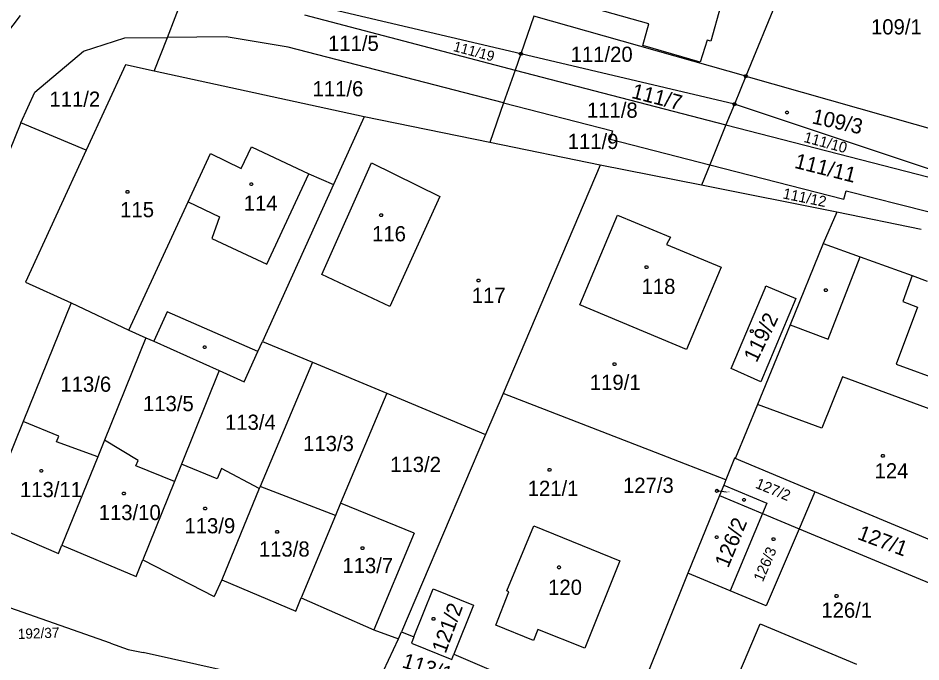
# Model space of a CAD drawing. Extents: x -634640 to -629202, y -1196156 to -1190068.
# Drawn here: x -631368.4 to -631267.3, y -1192828.3 to -1192756.2 of the extents above; entities that cross this region are included whole.
import ezdxf

# ---------------------------------------------------------------- set-up
doc = ezdxf.new("R2010")
doc.units = 0
for name, color, linetype in [('Vrstva 1', 7, 'Continuous'), ('Vrstva 2', 7, 'Continuous'), ('Vrstva 3', 7, 'Continuous'), ('Vrstva 4', 7, 'Continuous'), ('Vrstva 5', 7, 'Continuous'), ('Vrstva 7', 7, 'Continuous'), ('Vrstva 8', 7, 'Continuous')]:
    doc.layers.add(name, color=color, linetype=linetype)

msp = doc.modelspace()

# ---------------------------------------------------------------- linework, layer by layer
at = {"layer": 'Vrstva 1'}
for p, q in [((-631281.05, -1192748.42), (-631286.91, -1192762.74)), ((-631351.71, -1192758.38), (-631349.73, -1192753.3)), ((-631312.12, -1192760.23), (-631337.29, -1192754.33)), ((-631370.55, -1192759.01), (-631368.15, -1192755.91)), ((-631336.36, -1192755.87), (-631312.76, -1192762.05)), ((-631310.65, -1192756.02), (-631312.12, -1192760.23)), ((-631286.91, -1192762.74), (-631310.65, -1192756.02)), ((-631361.1, -1192759.91), (-631356.48, -1192758.44)), ((-631356.48, -1192758.44), (-631351.71, -1192758.38)), ((-631353.18, -1192762.15), (-631351.71, -1192758.38)), ((-631345.14, -1192758.3), (-631351.71, -1192758.38)), ((-631338.18, -1192759.46), (-631345.14, -1192758.3)), ((-631366.57, -1192764.5), (-631361.1, -1192759.91)), ((-631314.04, -1192765.69), (-631338.18, -1192759.46)), ((-631312.12, -1192760.23), (-631312.76, -1192762.05)), ((-631288.17, -1192765.84), (-631312.12, -1192760.23)), ((-631356.4, -1192761.45), (-631360.79, -1192771)), ((-631353.18, -1192762.15), (-631356.4, -1192761.45)), ((-631329.66, -1192767.28), (-631353.18, -1192762.15)), ((-631312.76, -1192762.05), (-631314.04, -1192765.69)), ((-631312.76, -1192762.05), (-631289.13, -1192768.17)), ((-631286.91, -1192762.74), (-631288.17, -1192765.84)), ((-631286.91, -1192762.74), (-631263.39, -1192769.4)), ((-631368.14, -1192767.96), (-631366.57, -1192764.5)), ((-631314.04, -1192765.69), (-631315.6, -1192770.16)), ((-631314.04, -1192765.69), (-631301.83, -1192768.84)), ((-631288.17, -1192765.84), (-631289.13, -1192768.17)), ((-631265.11, -1192773.56), (-631288.17, -1192765.84)), ((-631329.66, -1192767.28), (-631333.09, -1192774.84)), ((-631315.6, -1192770.16), (-631329.66, -1192767.28)), ((-631368.14, -1192767.96), (-631383.56, -1192806)), ((-631360.79, -1192771), (-631368.14, -1192767.96)), ((-631289.13, -1192768.17), (-631290.58, -1192771.73)), ((-631289.13, -1192768.17), (-631265.22, -1192774.34)), ((-631301.83, -1192768.84), (-631302.1, -1192769.76)), ((-631303.21, -1192772.69), (-631315.6, -1192770.16)), ((-631302.1, -1192769.76), (-631290.95, -1192772.64)), ((-631360.79, -1192771), (-631367.59, -1192785.78)), ((-631349.38, -1192776.81), (-631346.87, -1192771.38)), ((-631346.87, -1192771.38), (-631343.46, -1192773.07)), ((-631343.46, -1192773.07), (-631342.28, -1192770.63)), ((-631342.28, -1192770.63), (-631335.86, -1192773.65)), ((-631290.58, -1192771.73), (-631290.95, -1192772.64)), ((-631334.42, -1192784.94), (-631328.83, -1192772.44)), ((-631328.83, -1192772.44), (-631321.18, -1192776.21)), ((-631303.21, -1192772.69), (-631314.1, -1192798.26)), ((-631291.89, -1192774.93), (-631303.21, -1192772.69)), ((-631290.95, -1192772.64), (-631291.89, -1192774.93)), ((-631290.95, -1192772.64), (-631275.92, -1192776.51)), ((-631335.86, -1192773.65), (-631333.09, -1192774.84)), ((-631333.09, -1192774.84), (-631341.04, -1192792.42)), ((-631276.72, -1192777.95), (-631291.89, -1192774.93)), ((-631321.18, -1192776.21), (-631326.78, -1192788.5)), ((-631275.92, -1192776.51), (-631275.65, -1192775.56)), ((-631275.65, -1192775.56), (-631266.53, -1192777.88)), ((-631356.03, -1192791.15), (-631349.38, -1192776.81)), ((-631305.5, -1192788.35), (-631301.27, -1192778.28)), ((-631301.27, -1192778.28), (-631295.36, -1192780.76)), ((-631276.72, -1192777.95), (-631278.23, -1192781.46)), ((-631267.27, -1192779.89), (-631276.72, -1192777.95)), ((-631295.36, -1192780.76), (-631295.78, -1192781.56)), ((-631278.23, -1192781.46), (-631281.94, -1192790.56)), ((-631278.23, -1192781.46), (-631274.09, -1192782.94)), ((-631295.78, -1192781.56), (-631289.67, -1192784.13)), ((-631274.09, -1192782.94), (-631268.29, -1192785.04)), ((-631289.77, -1192784.36), (-631293.55, -1192793.33)), ((-631289.67, -1192784.13), (-631289.77, -1192784.36)), ((-631326.78, -1192788.5), (-631334.42, -1192784.94)), ((-631268.29, -1192785.04), (-631266.59, -1192785.68)), ((-631367.59, -1192785.78), (-631362.5, -1192788.1)), ((-631284.75, -1192786.45), (-631284.65, -1192786.22)), ((-631362.5, -1192788.1), (-631367.88, -1192801.41)), ((-631362.5, -1192788.1), (-631356.03, -1192791.15)), ((-631293.55, -1192793.33), (-631305.5, -1192788.35)), ((-631281.94, -1192790.56), (-631285.59, -1192799.48)), ((-631356.03, -1192791.15), (-631354.11, -1192792.01)), ((-631354.11, -1192792.01), (-631358.75, -1192803.49)), ((-631354.11, -1192792.01), (-631353.23, -1192792.4)), ((-631353.23, -1192792.4), (-631345.9, -1192795.69)), ((-631341.56, -1192793.56), (-631341.04, -1192792.42)), ((-631341.04, -1192792.42), (-631335.44, -1192794.76)), ((-631343.09, -1192796.95), (-631341.56, -1192793.56)), ((-631345.9, -1192795.69), (-631350.14, -1192806.19)), ((-631345.9, -1192795.69), (-631343.09, -1192796.95)), ((-631335.44, -1192794.76), (-631341.32, -1192808.68)), ((-631335.44, -1192794.76), (-631327.13, -1192798.23)), ((-631276.09, -1192796.41), (-631278.39, -1192802.13)), ((-631256.23, -1192803.72), (-631276.09, -1192796.41)), ((-631327.13, -1192798.23), (-631332.31, -1192810.53)), ((-631327.13, -1192798.23), (-631316.06, -1192802.86)), ((-631314.1, -1192798.26), (-631316.06, -1192802.86)), ((-631297.04, -1192804.88), (-631314.1, -1192798.26)), ((-631285.59, -1192799.48), (-631288.08, -1192805.45)), ((-631278.39, -1192802.13), (-631285.59, -1192799.48)), ((-631367.88, -1192801.41), (-631372.38, -1192812.53)), ((-631363.87, -1192803.03), (-631367.88, -1192801.41)), ((-631364.13, -1192803.68), (-631363.87, -1192803.03)), ((-631359.5, -1192805.34), (-631364.13, -1192803.68)), ((-631358.75, -1192803.49), (-631359.5, -1192805.34)), ((-631355, -1192805.78), (-631358.75, -1192803.49)), ((-631316.06, -1192802.86), (-631325.47, -1192824.94)), ((-631359.5, -1192805.34), (-631363.52, -1192815.26)), ((-631355.23, -1192806.36), (-631355, -1192805.78)), ((-631289.16, -1192807.93), (-631297.04, -1192804.88)), ((-631288.18, -1192805.52), (-631289.16, -1192807.93)), ((-631288.08, -1192805.45), (-631288.18, -1192805.52)), ((-631279.18, -1192809.27), (-631288.18, -1192805.52)), ((-631350.92, -1192808.11), (-631355.23, -1192806.36)), ((-631350.14, -1192806.19), (-631350.92, -1192808.11)), ((-631346.12, -1192807.81), (-631350.14, -1192806.19)), ((-631345.65, -1192806.65), (-631346.12, -1192807.81)), ((-631341.41, -1192808.91), (-631345.65, -1192806.65)), ((-631350.92, -1192808.11), (-631354.47, -1192816.89)), ((-631341.32, -1192808.68), (-631341.41, -1192808.91)), ((-631332.89, -1192811.91), (-631341.32, -1192808.68)), ((-631289.39, -1192808.51), (-631289.87, -1192809.7)), ((-631289.16, -1192807.93), (-631289.39, -1192808.51)), ((-631289.39, -1192808.51), (-631284.57, -1192810.54)), ((-631341.41, -1192808.91), (-631345.62, -1192819.12)), ((-631289.87, -1192809.7), (-631293.39, -1192818.39)), ((-631289.87, -1192809.7), (-631285.05, -1192811.71)), ((-631279.18, -1192809.27), (-631280.95, -1192813.42)), ((-631261.48, -1192816.65), (-631279.18, -1192809.27)), ((-631332.31, -1192810.53), (-631332.89, -1192811.91)), ((-631324.05, -1192813.9), (-631332.31, -1192810.53)), ((-631284.57, -1192810.54), (-631285.05, -1192811.71)), ((-631285.05, -1192811.71), (-631288.65, -1192820.38)), ((-631285.05, -1192811.71), (-631280.95, -1192813.42)), ((-631372.38, -1192812.53), (-631363.89, -1192816.19)), ((-631332.89, -1192811.91), (-631336.71, -1192821.16)), ((-631324.05, -1192813.9), (-631328.57, -1192824.73)), ((-631313.67, -1192820.35), (-631310.66, -1192813.1)), ((-631310.66, -1192813.1), (-631301.01, -1192817)), ((-631280.95, -1192813.42), (-631284.64, -1192822.06)), ((-631280.95, -1192813.42), (-631263.19, -1192820.82)), ((-631363.89, -1192816.19), (-631363.52, -1192815.26)), ((-631363.52, -1192815.26), (-631355.22, -1192818.74)), ((-631355.22, -1192818.74), (-631354.47, -1192816.89)), ((-631354.47, -1192816.89), (-631346.47, -1192821.01)), ((-631301.01, -1192817), (-631304.93, -1192826.8)), ((-631293.39, -1192818.39), (-631300.37, -1192835.66)), ((-631288.65, -1192820.38), (-631293.39, -1192818.39)), ((-631345.62, -1192819.12), (-631346.47, -1192821.01)), ((-631345.62, -1192819.12), (-631337.33, -1192822.64)), ((-631358.1, -1192826.22), (-631375.46, -1192820.15)), ((-631314.91, -1192824.2), (-631313.44, -1192820.46)), ((-631313.44, -1192820.46), (-631313.67, -1192820.35)), ((-631284.64, -1192822.06), (-631288.65, -1192820.38)), ((-631337.33, -1192822.64), (-631336.71, -1192821.16)), ((-631336.71, -1192821.16), (-631328.57, -1192824.73)), ((-631328.57, -1192824.73), (-631325.8, -1192825.72)), ((-631325.8, -1192825.72), (-631325.47, -1192824.94)), ((-631325.47, -1192824.94), (-631324.09, -1192825.53)), ((-631310.69, -1192825.91), (-631314.91, -1192824.2)), ((-631310.21, -1192824.7), (-631310.69, -1192825.91)), ((-631304.93, -1192826.8), (-631310.21, -1192824.7)), ((-631289.75, -1192834.57), (-631285.31, -1192824.07)), ((-631285.31, -1192824.07), (-631274.5, -1192828.59)), ((-631327.48, -1192829.33), (-631325.8, -1192825.72)), ((-631358.1, -1192826.22), (-631356.1, -1192826.94)), ((-631356.1, -1192826.94), (-631354.44, -1192827.28)), ((-631336.95, -1192831.15), (-631354.44, -1192827.28)), ((-631319.61, -1192827.44), (-631301.4, -1192835.22))]:
    msp.add_line(p, q, dxfattribs=at)
for points in [[(-631306.68, -1192754.37), (-631304.51, -1192746.55), (-631302.7, -1192747.04), (-631302.07, -1192744.87), (-631296.98, -1192746.31), (-631297.63, -1192748.46), (-631288.66, -1192751), (-631290.81, -1192758.8), (-631291.23, -1192758.68), (-631292.01, -1192761.16), (-631298.44, -1192759.3), (-631297.77, -1192756.85), (-631306.68, -1192754.37)], [(-631284.65, -1192786.22), (-631281.32, -1192787.62), (-631285.23, -1192796.94), (-631288.56, -1192795.47), (-631284.75, -1192786.45)], [(-631324.09, -1192825.53), (-631321.92, -1192820.13), (-631317.4, -1192821.95), (-631319.61, -1192827.44)], [(-631324.09, -1192825.53), (-631324.38, -1192826.23), (-631319.85, -1192828.06), (-631319.61, -1192827.44)]]:
    msp.add_lwpolyline(points, dxfattribs=at)
at = {"layer": 'Vrstva 3'}
for points in [[(-631282.2, -1192766.64), (-631282.11, -1192766.79), (-631282.2, -1192766.94), (-631282.38, -1192766.94), (-631282.47, -1192766.79), (-631282.38, -1192766.64), (-631282.2, -1192766.64)], [(-631356.09, -1192775.53), (-631356, -1192775.68), (-631356.09, -1192775.83), (-631356.27, -1192775.83), (-631356.36, -1192775.68), (-631356.27, -1192775.53), (-631356.09, -1192775.53)], [(-631316.76, -1192785.46), (-631316.67, -1192785.61), (-631316.76, -1192785.76), (-631316.94, -1192785.76), (-631317.03, -1192785.61), (-631316.94, -1192785.46), (-631316.76, -1192785.46)], [(-631301.52, -1192794.83), (-631301.43, -1192794.98), (-631301.52, -1192795.13), (-631301.7, -1192795.13), (-631301.79, -1192794.98), (-631301.7, -1192794.83), (-631301.52, -1192794.83)], [(-631271.47, -1192805.08), (-631271.38, -1192805.23), (-631271.47, -1192805.38), (-631271.65, -1192805.38), (-631271.74, -1192805.23), (-631271.65, -1192805.08), (-631271.47, -1192805.08)], [(-631308.8, -1192806.67), (-631308.71, -1192806.82), (-631308.8, -1192806.97), (-631308.98, -1192806.97), (-631309.07, -1192806.82), (-631308.98, -1192806.67), (-631308.8, -1192806.67)], [(-631283.71, -1192814.41), (-631283.62, -1192814.56), (-631283.71, -1192814.71), (-631283.89, -1192814.71), (-631283.98, -1192814.56), (-631283.89, -1192814.41), (-631283.71, -1192814.41)], [(-631276.65, -1192820.79), (-631276.56, -1192820.94), (-631276.65, -1192821.09), (-631276.83, -1192821.09), (-631276.92, -1192820.94), (-631276.83, -1192820.79), (-631276.65, -1192820.79)]]:
    msp.add_lwpolyline(points, dxfattribs=at)
at = {"layer": 'Vrstva 4'}
for p, q in [((-631340.57, -1192783.78), (-631335.86, -1192773.65)), ((-631349.38, -1192776.81), (-631345.87, -1192778.48)), ((-631345.87, -1192778.48), (-631346.72, -1192780.89)), ((-631346.72, -1192780.89), (-631340.57, -1192783.78)), ((-631277.67, -1192792.17), (-631274.09, -1192782.94)), ((-631268.29, -1192785.04), (-631269.31, -1192787.96)), ((-631267.67, -1192788.58), (-631270.06, -1192794.98)), ((-631269.31, -1192787.96), (-631267.67, -1192788.58)), ((-631351.75, -1192789.13), (-631353.23, -1192792.4)), ((-631341.56, -1192793.56), (-631351.75, -1192789.13)), ((-631281.94, -1192790.56), (-631277.67, -1192792.17)), ((-631270.06, -1192794.98), (-631260.88, -1192798.34))]:
    msp.add_line(p, q, dxfattribs=at)
at = {"layer": 'Vrstva 5'}
for points in [[(-631342.21, -1192774.67), (-631342.12, -1192774.82), (-631342.21, -1192774.97), (-631342.39, -1192774.97), (-631342.48, -1192774.82), (-631342.39, -1192774.67), (-631342.21, -1192774.67)], [(-631327.68, -1192778.15), (-631327.59, -1192778.3), (-631327.68, -1192778.45), (-631327.86, -1192778.45), (-631327.95, -1192778.3), (-631327.86, -1192778.15), (-631327.68, -1192778.15)], [(-631297.94, -1192783.97), (-631297.85, -1192784.12), (-631297.94, -1192784.27), (-631298.12, -1192784.27), (-631298.21, -1192784.12), (-631298.12, -1192783.97), (-631297.94, -1192783.97)], [(-631277.85, -1192786.55), (-631277.76, -1192786.7), (-631277.85, -1192786.85), (-631278.03, -1192786.85), (-631278.12, -1192786.7), (-631278.03, -1192786.55), (-631277.85, -1192786.55)], [(-631286.14, -1192791.14), (-631286.05, -1192791.29), (-631286.14, -1192791.44), (-631286.32, -1192791.44), (-631286.41, -1192791.29), (-631286.32, -1192791.14), (-631286.14, -1192791.14)], [(-631347.44, -1192792.92), (-631347.35, -1192793.07), (-631347.44, -1192793.22), (-631347.62, -1192793.22), (-631347.71, -1192793.07), (-631347.62, -1192792.92), (-631347.44, -1192792.92)], [(-631365.74, -1192806.77), (-631365.65, -1192806.92), (-631365.74, -1192807.07), (-631365.92, -1192807.07), (-631366.01, -1192806.92), (-631365.92, -1192806.77), (-631365.74, -1192806.77)], [(-631356.51, -1192809.31), (-631356.42, -1192809.46), (-631356.51, -1192809.61), (-631356.69, -1192809.61), (-631356.78, -1192809.46), (-631356.69, -1192809.31), (-631356.51, -1192809.31)], [(-631287.02, -1192810.02), (-631286.93, -1192810.17), (-631287.02, -1192810.32), (-631287.2, -1192810.32), (-631287.29, -1192810.17), (-631287.2, -1192810.02), (-631287.02, -1192810.02)], [(-631347.38, -1192810.99), (-631347.29, -1192811.14), (-631347.38, -1192811.29), (-631347.56, -1192811.29), (-631347.65, -1192811.14), (-631347.56, -1192810.99), (-631347.38, -1192810.99)], [(-631339.32, -1192813.61), (-631339.23, -1192813.76), (-631339.32, -1192813.91), (-631339.5, -1192813.91), (-631339.59, -1192813.76), (-631339.5, -1192813.61), (-631339.32, -1192813.61)], [(-631290.09, -1192814.21), (-631290, -1192814.36), (-631290.09, -1192814.51), (-631290.27, -1192814.51), (-631290.36, -1192814.36), (-631290.27, -1192814.21), (-631290.09, -1192814.21)], [(-631329.76, -1192815.44), (-631329.67, -1192815.59), (-631329.76, -1192815.74), (-631329.94, -1192815.74), (-631330.03, -1192815.59), (-631329.94, -1192815.44), (-631329.76, -1192815.44)], [(-631307.75, -1192817.58), (-631307.66, -1192817.73), (-631307.75, -1192817.88), (-631307.93, -1192817.88), (-631308.02, -1192817.73), (-631307.93, -1192817.58), (-631307.75, -1192817.58)], [(-631321.81, -1192823.33), (-631321.72, -1192823.48), (-631321.81, -1192823.63), (-631321.99, -1192823.63), (-631322.08, -1192823.48), (-631321.99, -1192823.33), (-631321.81, -1192823.33)]]:
    msp.add_lwpolyline(points, dxfattribs=at)
at = {"layer": 'Vrstva 7'}
msp.add_line((-631289.12, -1192809.32), (-631290.15, -1192809.16), dxfattribs=at)
msp.add_lwpolyline([(-631290.284, -1192809.048), (-631290.122, -1192808.982), (-631289.988, -1192809.095), (-631290.016, -1192809.272), (-631290.178, -1192809.338), (-631290.312, -1192809.225), (-631290.284, -1192809.048)], dxfattribs=at)
at = {"layer": 'Vrstva 8'}
for points in [[(-631312.03, -1192760.08), (-631311.94, -1192760.23), (-631312.03, -1192760.38), (-631312.21, -1192760.38), (-631312.3, -1192760.23), (-631312.21, -1192760.08), (-631312.03, -1192760.08)], [(-631286.82, -1192762.59), (-631286.73, -1192762.74), (-631286.82, -1192762.89), (-631287, -1192762.89), (-631287.09, -1192762.74), (-631287, -1192762.59), (-631286.82, -1192762.59)], [(-631288.08, -1192765.69), (-631287.99, -1192765.84), (-631288.08, -1192765.99), (-631288.26, -1192765.99), (-631288.35, -1192765.84), (-631288.26, -1192765.69), (-631288.08, -1192765.69)]]:
    msp.add_lwpolyline(points, dxfattribs=at)

# ---------------------------------------------------------------- texts
at = {"layer": 'Vrstva 2'}
for s, height, p in [('109/1', 1.7, (-631272.887, -1192758.05)), ('111/5', 1.7, (-631333.717, -1192759.89)), ('111/20', 1.7, (-631306.537, -1192761.12)), ('111/6', 1.7, (-631335.447, -1192764.98)), ('111/2', 1.7, (-631364.927, -1192766.15)), ('111/8', 1.7, (-631304.707, -1192767.38)), ('111/9', 1.7, (-631306.867, -1192770.88)), ('114', 1.7, (-631343.157, -1192777.79)), ('115', 1.7, (-631356.997, -1192778.52)), ('116', 1.7, (-631328.777, -1192781.22)), ('118', 1.7, (-631298.587, -1192787.11)), ('117', 1.7, (-631317.607, -1192788.12)), ('113/6', 1.7, (-631363.697, -1192798.07)), ('119/1', 1.7, (-631304.384, -1192797.86)), ('113/5', 1.7, (-631354.447, -1192800.24)), ('113/4', 1.7, (-631345.257, -1192802.33)), ('113/3', 1.7, (-631336.507, -1192804.71)), ('113/2', 1.7, (-631326.747, -1192807.05)), ('124', 1.7, (-631272.487, -1192807.77)), ('113/11', 1.7, (-631368.227, -1192809.87)), ('121/1', 1.7, (-631311.344, -1192809.73)), ('127/3', 0.1, (-631289.097, -1192809.32)), ('113/10', 1.7, (-631359.407, -1192812.44)), ('113/9', 1.7, (-631349.797, -1192813.92)), ('113/8', 1.7, (-631341.457, -1192816.53)), ('113/7', 1.7, (-631332.107, -1192818.37)), ('120', 1.7, (-631309.057, -1192820.81)), ('126/1', 1.7, (-631278.447, -1192823.37))]:
    msp.add_text(s, height=height, dxfattribs=at).set_placement(p)
for s, height, rotation, p in [('111/19', 1.14, 345.09248, (-631319.753, -1192759.89)), ('111/7', 1.7, 345.55085, (-631299.81, -1192765.148)), ('109/3', 1.7, 347.32702, (-631279.587, -1192767.996)), ('111/10', 1.2, 344.806, (-631280.492, -1192770.073)), ('111/11', 1.7, 345.89462, (-631281.549, -1192772.976)), ('111/12', 1.2, 348.41564, (-631282.828, -1192776.406)), ('119/2', 1.7, 63.99939, (-631285.703, -1192794.885)), ('127/2', 1.2, 337.58673, (-631285.924, -1192808.796)), ('126/2', 1.7, 67.55173, (-631288.89, -1192817.887)), ('127/1', 1.7, 339.4202, (-631274.512, -1192814.538)), ('126/3', 1.19, 66.63499, (-631285.011, -1192819.438)), ('121/2', 1.7, 69.72896, (-631320.549, -1192827.466)), ('113/12', 1.7, 342.62876, (-631325.515, -1192828.907))]:
    msp.add_text(s, height=height, rotation=rotation, dxfattribs=at).set_placement(p)
at = {"layer": 'Vrstva 7'}
msp.add_text('127/3', height=1.7, dxfattribs=at).set_placement((-631300.672, -1192809.39))
msp.add_text('192/37', height=1.14, rotation=2.00535, dxfattribs=at).set_placement((-631368.45, -1192825.762))

doc.saveas('drawing.dxf')
